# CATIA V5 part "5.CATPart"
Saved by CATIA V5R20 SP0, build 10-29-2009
Part number: 5
Bounding box of the stored display mesh (mm): x -12.5 to 12.5, y -12.5 to 12.5, z -20 to 50
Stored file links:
  E:\Ehsan\Amoozesh\CATIA\CATIA Course\Advanced\Exercises\DMU Kinematic\11\5.CATPart
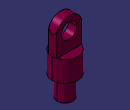
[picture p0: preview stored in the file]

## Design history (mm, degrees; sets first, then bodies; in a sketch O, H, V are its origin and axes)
Body1 (main body)
  Sketch1 on xy-plane, origin (0, 0, 0), H (1, 0, 0), V (0, 1, 0)
    circle A1 centre (0, 0) radius 12.5
    radius A1 = 12.5
  Pad1: profile Sketch1, direction (0, 0, 1), length 20
  Sketch2 on end face of Pad1, origin (0, 0, 20), H (1, 0, 0), V (0, 1, 0)
    line L1 (11.8427, -4) -> (-11.8427, -4)
    line L2 (-11.8427, 4) -> (11.8427, 4)
    projected circle E1 centre (0, 0) radius 12.5 from edge [face of Pad1 from Sketch1.A1 | end face of Pad1]
    projected arc E2 centre (0, 0) radius 12.5 from (-11.8427, 4) to (-11.8427, -4) ccw from edge [face of Pad1 from Sketch1.A1 | end face of Pad1]
    projected arc E3 centre (0, 0) radius 12.5 from (11.8427, -4) to (11.8427, 4) ccw from edge [face of Pad1 from Sketch1.A1 | end face of Pad1]
    point P1 (11.8427, 4)
    point P2 (-11.8427, 4)
    point P4 (11.8427, -4)
    point P5 (-11.8427, 4)
    point P6 (11.8427, -4)
    point P7 (11.8427, 4)
    distance L2 L1 = 8
    horizontal: L1 H, L2 H
    equidistance: L1 L2 O
    coincidence: L2 P1, L2 P2, L1 P4, E1 P5, E1 P6, E1 P7, P1 P7, P2 P5, P4 P6
  Pad2: profile Sketch2, direction (0, 0, 1), length 30
  Sketch3 on start face of Pad1, origin (0, 0, 0), H (1, 0, 0), V (0, -1, 0)
    circle A1 centre (0, 0) radius 7.5
    radius A1 = 7.5
  Pad3: profile Sketch3, direction (0, 0, -1), length 20
  Sketch4 on zx-plane, origin (0, 0, 0), H (-1, 0, 0), V (0, 0, 1)
    arc A1 centre (0, 37.5) radius 12.5 from (12.5, 37.5) to (-12.5, 37.5) ccw
    point P1 (0, 37.5)
    point P2 (12.5, 37.5)
    point P3 (-12.5, 37.5)
    reference projected line E1 (-11.8427, 50) -> (11.8427, 50) from edge [face of Pad2 from Sketch2.L2 | end face of Pad2]
    reference intersected point E2 (12.5, 50) from edge [face of Pad2 | end face of Pad2]
    axis line L1 (12.5, 50) -> (12.5, 34.5692)
    point P4 (12.5, 34.5692)
    point P5 (-12.5, 34.5692)
    construction line L2 (-12.5, 50) -> (-12.5, 34.5692)
    point P6 (-12.5, 50)
    coincidence: P1 V, P2 L1
    tangency: A1 E1, A1 L1
    vertical: L1 V
    symmetry: P4 P5 V, L1 L2 V, E2 P6 V, P3 P2 V
  Pocket1: profile Sketch4, direction (0, -1, 0), through (limit type 6), opposite side through (limit type 6)
  Sketch5 on face of Pad2 from Sketch2.L2, origin (0, 4, 0), H (-1, 0, 0), V (0, 0, 1)
    circle A1 centre (0, 37.5) radius 7.5
    point P1 (0, 37.5)
    reference projected arc E1 centre (0, 37.5) radius 12.5 from (11.8427, 41.5) to (-11.8427, 41.5) ccw from edge [face of Pad2 from Sketch2.L2 | face of Pocket1]
    radius A1 = 7.5
    coincidence: P1 V
    concentricity: A1 E1
  Pocket2: profile Sketch5, direction (0, -1, 0), through (limit type 6)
